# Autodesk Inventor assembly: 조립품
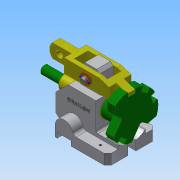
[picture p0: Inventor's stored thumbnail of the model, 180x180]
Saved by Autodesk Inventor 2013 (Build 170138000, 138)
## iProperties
Created: 2016-11
Part Number: 조립품
Document SubType Name: Assembly
Designer: Administrator
Author: Administrator
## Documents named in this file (8)
- C:\Users\Administrator\Desktop\461108V1021\조립품.iam
- C:\Users\Administrator\Desktop\461108V1021\본체.ipt
- C:\Users\Administrator\Desktop\461108V1021\부시.ipt
- C:\Users\Administrator\Desktop\461108V1021\분할대.ipt
- C:\Users\Administrator\Desktop\461108V1021\분할축.ipt
- C:\Users\Administrator\Desktop\461108V1021\와셔.ipt
- C:\Users\Administrator\Desktop\461108V1021\원통형핀.ipt
- C:\Users\Administrator\Desktop\461108V1021\클레비스핀.ipt
